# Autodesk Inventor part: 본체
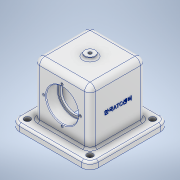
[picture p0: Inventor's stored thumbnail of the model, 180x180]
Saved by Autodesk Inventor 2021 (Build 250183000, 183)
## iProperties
Created: 2022-07
Part Number: 본체
Material: 알루미늄 6061
Document SubType Name: Modeling
Designer: cwnu10
Mass: 1059.83 g
Surface Area: 721.846 cm^2
Volume: 392.53 cm^3
Density: 2.7 g/cm^3
Appearance: 알루미늄 - 평지
Author: cwnu10
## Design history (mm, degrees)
sketch "스케치1"
  geometry: L1 (58, -58)-(-58, -58); L2 (-58, -58)-(-58, 58); L3 (-58, 58)-(58, 58); L4 (58, 58)-(58, -58); L5 (58, -58)-(-58, 58); L6 (-58, -58)-(58, 58); 1 further point
  constraints: 12 end point, 2 midpoint, 2 parallel, 2 perpendicular, 1 horizontal
  dimensions: "d0" = 116 distance of L2.end L3.end
extrude "돌출1" new body sketch "스케치1" distance "d1" = 10; taper "d2" = 0 deg
sketch "스케치2"
  geometry: L1 (41, -41)-(-41, -41); L2 (-41, -41)-(-41, 41); L3 (-41, 41)-(41, 41); L4 (41, 41)-(41, -41); L5 (41, -41)-(-41, 41); L6 (-41, -41)-(41, 41); 1 further point
  constraints: 12 end point, 2 midpoint, 2 parallel, 2 perpendicular, 1 horizontal
  dimensions: "d3" = 82 distance of L1.start L1.end
extrude "돌출2" join sketch "스케치2" distance "d4" = 90; taper "d5" = 0 deg
fillet "모깎기1" dims "d6" = 12
fillet "모깎기2" dims "d7" = 8
sketch "스케치3"
  geometry: L1 (0, -46)-(0, 46) reference; C1 r 20 at (48, 0); 2 further points
  constraints: 1 centre point, 1 horizontal alignment, 1 midpoint
  dimensions: "d8" = 40 diameter of C1; "d9" = 48 distance from line of C1.centre L1
extrude "돌출3" cut sketch "스케치3" extent not by distance; stored distance "d10" = 0; taper "d11" = 0 deg
sketch "스케치4"
  geometry: C1 r 20 at (33, 38) reference; 2 further points
  constraints: 1 coincident
hole "구멍1" sketch "스케치4" at (33, 38) diameter "d12" = 47; stored, may be unused: countersink angle "d16" = 90 deg, drill point angle "d18" = 0 deg; dims "d13" = 6, "d14" = 4, "d15" = 2, "d17" = 17
sketch "스케치5"
  geometry: C1 r 23.5 at (33, 38) reference; A1 r 27 centre (33, 38) between (33, 65) and (33, 11); 3 further points
  constraints: 4 point on circle, 2 horizontal alignment, 2 vertical alignment, 1 centre point, 1 coincident
  dimensions: "d23" = 54 diameter of A1
hole "구멍2" sketch "스케치5" at (33, 65), (33, 11), (60, 38), (6, 38) diameter "d24" = 3.242; stored, may be unused: countersink angle "d28" = 90 deg, drill point angle "d30" = 118 deg; dims "d25" = 8, "d26" = 4, "d27" = 2, "d29" = 10
fillet "모깎기4" dims "d31" = 0.6
chamfer "모따기2" distance "d32" = 1; stored, may be unused: second distance "d33" = 2, angle "d34" = 45 deg
sketch "스케치6"
  geometry: C1 r 7.5 at (0, 0); 1 further point
  constraints: 1 centre point, 1 coincident
  dimensions: "d35" = 15 diameter of C1
extrude "돌출4" join sketch "스케치6" distance "d36" = 4; taper "d37" = 0 deg
fillet "모깎기5" dims "d38" = 8
sketch "스케치7"
  geometry: L1 (-21, 30)-(21, 30); L2 (21, 30)-(21, -30); L3 (21, -30)-(-21, -30); L4 (-21, -30)-(-21, 30); L5 (-21, 30)-(21, -30); L6 (21, 30)-(-21, -30); 1 further point
  constraints: 12 end point, 2 midpoint, 2 parallel, 1 horizontal, 1 perpendicular
  dimensions: "d39" = 42 distance of L2.end L3.end; "d40" = 60 distance of L1.end L2.end
extrude "돌출5" cut sketch "스케치7" distance "d41" = 80; taper "d42" = 0 deg
fillet "모깎기6" dims "d43" = 3
fillet "모깎기7" dims "d44" = 3
sketch "스케치8"
  geometry: A1 r 12 centre (-46, 46) between (-46, 58) and (-58, 46) reference; A2 r 12 centre (46, 46) between (58, 46) and (46, 58) reference; A3 r 12 centre (46, -46) between (46, -58) and (58, -46) reference; A4 r 12 centre (-46, -46) between (-58, -46) and (-46, -58) reference; 1 further point
hole "구멍3" sketch "스케치8" at (-46, -46), (-46, 46), (46, 46), (46, -46) diameter "d45" = 9; stored, may be unused: countersink angle "d49" = 90 deg, drill point angle "d51" = 0 deg; dims "d46" = 8, "d47" = 4, "d48" = 2, "d50" = 10
sketch "스케치9"
  geometry: C1 r 7.5 at (0, 0) reference; 2 further points
  constraints: 1 coincident
hole "구멍4" sketch "스케치9" at (0, 0) diameter "d52" = 4.917; stored, may be unused: countersink angle "d56" = 90 deg, drill point angle "d58" = 0 deg; dims "d53" = 99, "d54" = 4, "d55" = 2, "d57" = 10
sketch "스케치10"
  geometry: L1 (-13, -82)-(79, -82) reference; 3 further points
  constraints: 1 midpoint, 1 vertical alignment, 1 other
  dimensions: "d59" = 48 distance of point (33, -82) point (33, -34)
extrude "돌출6" join sketch "스케치10" distance "d60" = 0.5; taper "d61" = 0 deg
node "솔리드1"
mirror "미러1"
feature "A9D066F2-1C7D-4E18-AEED-F7BC21143FA4" dims "d12" = 47, "d13" = 6, "d14" = 4, "d15" = 2, "d16" = 90 deg, "d17" = 17, "d18" = 0
